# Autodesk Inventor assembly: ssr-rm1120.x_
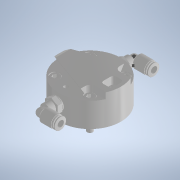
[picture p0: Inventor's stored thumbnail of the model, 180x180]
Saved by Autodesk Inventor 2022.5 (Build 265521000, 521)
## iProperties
Created: 2022-03
Part Number: ssr-rm1120.x_
Document SubType Name: Assembly
Designer: ImaoCorp
Sending System: SOLIDWORKS 2020-2020296
MC: AMD64
MC_MODEL: Intel64 Family 6 Model 60 Stepping 3, GenuineIntel
OS: Windows_NT
FRU: Parasolid Version 31.1, build 290,  3- 9-2020
FORMAT: text
GUISE: transmit
KEY: ssr-rm1120
FILE: ssr-rm1120.x_t
DATE: Mon Mar  7 09:50:24 2022
Author: ImaoCorp
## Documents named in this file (4)
- X:\14_SW2022-Inv2022\00_全2023-1023新製品(TCC)まで\s\ssr-rm1120\SSR-RM1120.iam
- X:\14_SW2022-Inv2022\00_全2023-1023新製品(TCC)まで\s\ssr-rm1120\ssr-rm1120_01.ipt
- X:\14_SW2022-Inv2022\00_全2023-1023新製品(TCC)まで\s\ssr-rm1120\ssr-rm1120_02.ipt
- X:\14_SW2022-Inv2022\00_全2023-1023新製品(TCC)まで\s\ssr-rm1120\ssr-rm1120_03.ipt
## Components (3 placed, 3 different names)
1. ssr-rm1120_01
2. ssr-rm1120_02
3. ssr-rm1120_03
